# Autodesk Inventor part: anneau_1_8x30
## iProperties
Created: 2011-01
Part Number: anneau_1_8x30
Document SubType Name: Modeling
Designer: eric
Density: 1 g/cm^3
Mass: 0.239831 g
Surface Area: 5.32959 cm^2
Volume: 0.239831 cm^3
Author: eric
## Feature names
1. Base1
